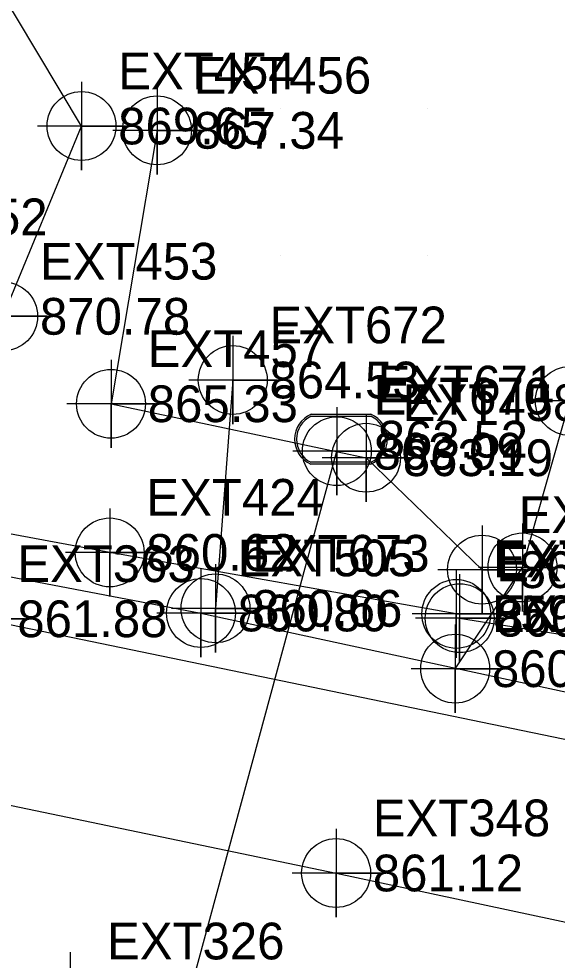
# Model space of a CAD drawing. Extents: x 1762120 to 1766775, y 709485 to 712965.
# Drawn here: x 1762642.2 to 1762678.8, y 712662 to 712726.1 of the extents above; entities that cross this region are included whole.
import ezdxf

# ---------------------------------------------------------------- set-up
doc = ezdxf.new("R2010")
doc.units = 0
for name, color, linetype in [('Exist DTM Breakline', 7, 'Continuous'), ('Exist DTM Breakline Cogo Elevation', 7, 'Continuous'), ('Exist DTM Breakline Cogo Number', 7, 'Continuous'), ('Exist DTM Breakline Cogo Point CELL', 7, 'Continuous'), ('Exist DTM Crownline', 7, 'Continuous'), ('Exist DTM Crownline Cogo Elevation', 7, 'Continuous'), ('Exist DTM Crownline Cogo Number', 7, 'Continuous'), ('Exist DTM Crownline Cogo Point CELL', 7, 'Continuous'), ('Exist DTM Drainline', 7, 'Continuous'), ('Exist DTM Drainline Cogo Elevation', 7, 'Continuous'), ('Exist DTM Drainline Cogo Number', 7, 'Continuous'), ('Exist DTM Drainline Cogo Point CELL', 7, 'Continuous'), ('Exist DTM QL2 LIDAR Elevation Point', 7, 'Continuous'), ('Exist Roads EOP', 7, 'Continuous'), ('Exist Roads EOP Cogo Elevation', 7, 'Continuous'), ('Exist Roads EOP Cogo Number', 7, 'Continuous'), ('Exist Roads EOP Cogo Point CELL', 7, 'Continuous'), ('Exist Roads EOP Other', 7, 'Continuous'), ('Exist Roads EOP Other Cogo Elevation', 7, 'Continuous'), ('Exist Roads EOP Other Cogo Number', 7, 'Continuous'), ('Exist Roads EOP Other Cogo Point CELL', 7, 'Continuous'), ('Exist Structure Minor Pipes RCP 12 Inch', 7, 'Continuous'), ('Exist Structure Minor Pipes RCP 12 Inch Cogo Comment', 7, 'Continuous'), ('Exist Structure Minor Pipes RCP 12 Inch Cogo Number', 7, 'Continuous'), ('Exist Structure Minor Pipes RCP 12 Inch Cogo Point CELL', 7, 'Continuous'), ('Exist Utilities Gas UG Line SUE LOS C', 7, 'Continuous'), ('Exist Utilities Gas UG Line SUE LOS C Cogo Elevation', 7, 'Continuous'), ('Exist Utilities Gas UG Line SUE LOS C Cogo Number', 7, 'Continuous'), ('Exist Utilities Gas UG Line SUE LOS C Cogo Point CELL', 7, 'Continuous'), ('Exist Utilities Water Meter CELL', 7, 'Continuous'), ('Exist Utilities Water Meter Cogo Elevation', 7, 'Continuous'), ('Exist Utilities Water Meter Cogo Number', 7, 'Continuous'), ('Exist Utilities Water UG Line SUE LOS C', 7, 'Continuous'), ('Exist Utilities Water UG Line SUE LOS C Cogo Elevation', 7, 'Continuous'), ('Exist Utilities Water UG Line SUE LOS C Cogo Number', 7, 'Continuous'), ('Exist Utilities Water UG Line SUE LOS C Cogo Point CELL', 7, 'Continuous')]:
    doc.layers.add(name, color=color, linetype=linetype)

msp = doc.modelspace()

# ---------------------------------------------------------------- linework, layer by layer
at = {"layer": 'Exist DTM Breakline'}
for points in [[(1762269.749, 712786.474), (1762271.078, 712779.952), (1762292.948, 712778.898), (1762320.699, 712776.029), (1762354.473, 712776.478), (1762388.07, 712765.375), (1762412.806, 712762.42), (1762443.018, 712756.652), (1762473.164, 712749.141), (1762494.52, 712743.823), (1762529.008, 712735.946), (1762558.208, 712731.146), (1762590.651, 712721.473), (1762629.546, 712708.877), (1762641.105, 712705.857), (1762646.432, 712718.811), (1762637.496, 712733.743)], [(1762651.575, 712718.518), (1762648.445, 712699.904), (1762665.806, 712696.23), (1762673.7, 712688.607)]]:
    msp.add_lwpolyline(points, dxfattribs=at)
at = {"layer": 'Exist DTM Breakline Cogo Point CELL'}
for points in [[(1762646.432, 712721.811), (1762646.432, 712715.811), (1762646.432, 712718.811), (1762649.432, 712718.811), (1762643.432, 712718.811)], [(1762651.575, 712721.518), (1762651.575, 712715.518), (1762651.575, 712718.518), (1762654.575, 712718.518), (1762648.575, 712718.518)], [(1762641.105, 712708.857), (1762641.105, 712702.857), (1762641.105, 712705.857), (1762644.105, 712705.857), (1762638.105, 712705.857)], [(1762648.445, 712702.904), (1762648.445, 712696.904), (1762648.445, 712699.904), (1762651.445, 712699.904), (1762645.445, 712699.904)], [(1762665.806, 712699.23), (1762665.806, 712693.23), (1762665.806, 712696.23), (1762668.806, 712696.23), (1762662.806, 712696.23)], [(1762673.7, 712691.607), (1762673.7, 712685.607), (1762673.7, 712688.607), (1762676.7, 712688.607), (1762670.7, 712688.607)]]:
    msp.add_lwpolyline(points, dxfattribs=at)
for centre in [(1762646.432, 712718.811), (1762651.575, 712718.518), (1762641.105, 712705.857), (1762648.445, 712699.904), (1762665.806, 712696.23), (1762673.7, 712688.607)]:
    msp.add_circle(centre, 2.344, dxfattribs=at)
at = {"layer": 'Exist DTM Crownline'}
msp.add_lwpolyline([(1762166.547, 712774.687), (1762217.293, 712763.929), (1762266.928, 712753.164), (1762315.989, 712742.645), (1762361.304, 712733.127), (1762409.518, 712722.711), (1762461.505, 712711.505), (1762512.117, 712700.307), (1762561.004, 712689.861), (1762611.478, 712678.845), (1762663.765, 712667.96), (1762715.266, 712656.972), (1762767.733, 712645.753), (1762820.16, 712634.416), (1762873.558, 712623.116), (1762907.318, 712615.867), (1762954.844, 712607.608), (1762970.656, 712604.722)], dxfattribs=at)
at = {"layer": 'Exist DTM Crownline Cogo Point CELL'}
msp.add_lwpolyline([(1762663.765, 712670.96), (1762663.765, 712664.96), (1762663.765, 712667.96), (1762666.765, 712667.96), (1762660.765, 712667.96)], dxfattribs=at)
msp.add_circle((1762663.765, 712667.96), 2.344, dxfattribs=at)
at = {"layer": 'Exist DTM Drainline'}
msp.add_lwpolyline([(1762671.946, 712685.598), (1762648.351, 712689.784), (1762626.117, 712693.918), (1762597.991, 712699.605), (1762564.625, 712706.389), (1762531.738, 712713.297), (1762498.472, 712720.195), (1762464.805, 712728.399), (1762431.886, 712735.459), (1762397.077, 712742.592), (1762358.768, 712750.543), (1762329.325, 712757.658), (1762298.805, 712765.159), (1762269.773, 712772.557), (1762248.853, 712776.111)], dxfattribs=at)
at = {"layer": 'Exist DTM Drainline Cogo Point CELL'}
for points in [[(1762648.351, 712692.784), (1762648.351, 712686.784), (1762648.351, 712689.784), (1762651.351, 712689.784), (1762645.351, 712689.784)], [(1762671.946, 712688.598), (1762671.946, 712682.598), (1762671.946, 712685.598), (1762674.946, 712685.598), (1762668.946, 712685.598)]]:
    msp.add_lwpolyline(points, dxfattribs=at)
for centre in [(1762648.351, 712689.784), (1762671.946, 712685.598)]:
    msp.add_circle(centre, 2.344, dxfattribs=at)
at = {"layer": 'Exist DTM QL2 LIDAR Elevation Point'}
for p, q in [((1762660, 712720), (1762660, 712720)), ((1762670, 712720), (1762670, 712720)), ((1762660, 712710), (1762660, 712710)), ((1762670, 712710), (1762670, 712710)), ((1762660, 712700), (1762660, 712700)), ((1762670, 712700), (1762670, 712700))]:
    msp.add_line(p, q, dxfattribs=at)
at = {"layer": 'Exist Roads EOP'}
msp.add_lwpolyline([(1762972.643, 712616.327), (1762930.479, 712622.907), (1762881.99, 712633.196), (1762831.971, 712644.063), (1762782.816, 712654.409), (1762735.737, 712664.412), (1762686.68, 712675.525), (1762639.564, 712685.265), (1762589.399, 712696.151), (1762546.232, 712705.49), (1762496.404, 712716.081), (1762446.151, 712726.895), (1762396.234, 712737.694), (1762346.428, 712748.231), (1762295.972, 712759.182), (1762245.105, 712770.099), (1762193.683, 712780.972), (1762169.004, 712786.417)], dxfattribs=at)
at = {"layer": 'Exist Roads EOP Cogo Point CELL'}
for points in [[(1762639.564, 712688.265), (1762639.564, 712682.265), (1762639.564, 712685.265), (1762642.564, 712685.265), (1762636.564, 712685.265)], [(1762645.671, 712662.578), (1762645.671, 712656.578), (1762645.671, 712659.578), (1762648.671, 712659.578), (1762642.671, 712659.578)]]:
    msp.add_lwpolyline(points, dxfattribs=at)
at = {"layer": 'Exist Roads EOP Other'}
msp.add_lwpolyline([(1762671.874, 712681.868), (1762676.456, 712688.763), (1762679.673, 712700.094), (1762681.831, 712712.591)], dxfattribs=at)
at = {"layer": 'Exist Roads EOP Other Cogo Point CELL'}
for points in [[(1762679.673, 712703.094), (1762679.673, 712697.094), (1762679.673, 712700.094), (1762682.673, 712700.094), (1762676.673, 712700.094)], [(1762676.456, 712691.763), (1762676.456, 712685.763), (1762676.456, 712688.763), (1762679.456, 712688.763), (1762673.456, 712688.763)], [(1762671.874, 712684.868), (1762671.874, 712678.868), (1762671.874, 712681.868), (1762674.874, 712681.868), (1762668.874, 712681.868)]]:
    msp.add_lwpolyline(points, dxfattribs=at)
for centre in [(1762679.673, 712700.094), (1762676.456, 712688.763), (1762671.874, 712681.868)]:
    msp.add_circle(centre, 2.344, dxfattribs=at)
at = {"layer": 'Exist Structure Minor Pipes RCP 12 Inch'}
msp.add_line((1762672.176, 712685.305), (1762690.378, 712682.399), dxfattribs=at)
at = {"layer": 'Exist Structure Minor Pipes RCP 12 Inch Cogo Point CELL'}
msp.add_lwpolyline([(1762672.176, 712688.305), (1762672.176, 712682.305), (1762672.176, 712685.305), (1762675.176, 712685.305), (1762669.176, 712685.305)], dxfattribs=at)
msp.add_circle((1762672.176, 712685.305), 2.344, dxfattribs=at)
at = {"layer": 'Exist Utilities Gas UG Line SUE LOS C'}
msp.add_line((1762656.73, 712701.52), (1762655.552, 712685.976), dxfattribs=at)
msp.add_lwpolyline([(1762186.211, 712786.583), (1762241.953, 712774.527), (1762368.977, 712745.664), (1762446.664, 712730.32), (1762499.183, 712718.668), (1762560.329, 712705.064), (1762614.265, 712693.34), (1762654.566, 712685.659), (1762695.772, 712676.761), (1762747.569, 712665.846), (1762826.119, 712649.314), (1762887.977, 712636.743)], dxfattribs=at)
at = {"layer": 'Exist Utilities Gas UG Line SUE LOS C Cogo Point CELL'}
for points in [[(1762656.73, 712704.52), (1762656.73, 712698.52), (1762656.73, 712701.52), (1762659.73, 712701.52), (1762653.73, 712701.52)], [(1762655.552, 712688.976), (1762655.552, 712682.976), (1762655.552, 712685.976), (1762658.552, 712685.976), (1762652.552, 712685.976)], [(1762654.566, 712688.659), (1762654.566, 712682.659), (1762654.566, 712685.659), (1762657.566, 712685.659), (1762651.566, 712685.659)]]:
    msp.add_lwpolyline(points, dxfattribs=at)
for centre in [(1762656.73, 712701.52), (1762655.552, 712685.976), (1762654.566, 712685.659)]:
    msp.add_circle(centre, 2.344, dxfattribs=at)
at = {"layer": 'Exist Utilities Water Meter CELL'}
msp.add_line((1762664.102, 712697.491), (1762664.102, 712697.491), dxfattribs=at)
for points in [[(1762662.065, 712699.191), (1762666.14, 712699.191)], [(1762662.065, 712699.053), (1762666.14, 712699.053)], [(1762666.14, 712695.928), (1762662.039, 712695.928)], [(1762666.14, 712695.791), (1762662.039, 712695.791)]]:
    msp.add_lwpolyline(points, dxfattribs=at)
for centre, radius, start, end in [((1762662.795, 712697.486), 1.855, 113.17804, 245.97939), ((1762662.806, 712697.485), 1.735, 115.30093, 243.78236), ((1762665.395, 712697.492), 1.856, 293.64832, 66.30838), ((1762665.407, 712697.491), 1.726, 295.12717, 64.87283)]:
    msp.add_arc(centre, radius, start, end, dxfattribs=at)
at = {"layer": 'Exist Utilities Water UG Line SUE LOS C'}
msp.add_line((1762652.797, 712656.06), (1762663.818, 712696.673), dxfattribs=at)
at = {"layer": 'Exist Utilities Water UG Line SUE LOS C Cogo Point CELL'}
msp.add_lwpolyline([(1762663.818, 712699.673), (1762663.818, 712693.673), (1762663.818, 712696.673), (1762666.818, 712696.673), (1762660.818, 712696.673)], dxfattribs=at)
msp.add_circle((1762663.818, 712696.673), 2.344, dxfattribs=at)

# ---------------------------------------------------------------- texts
at = {"layer": 'Exist DTM Breakline Cogo Elevation'}
for s, p in [('869.65', (1762648.932, 712717.561)), ('867.34', (1762654.075, 712717.268)), ('870.78', (1762643.605, 712704.607)), ('865.33', (1762650.945, 712698.654)), ('863.19', (1762668.306, 712694.98)), ('861.20', (1762676.2, 712687.357))]:
    msp.add_text(s, height=2.5, dxfattribs=at).set_placement(p)
at = {"layer": 'Exist DTM Breakline Cogo Number'}
for s, p in [('EXT454', (1762648.932, 712721.311)), ('EXT456', (1762654.075, 712721.018)), ('EXT452', (1762632.046, 712711.377)), ('EXT453', (1762643.605, 712708.357)), ('EXT457', (1762650.945, 712702.404)), ('EXT458', (1762668.306, 712698.73)), ('EXT459', (1762676.2, 712691.107))]:
    msp.add_text(s, height=2.5, dxfattribs=at).set_placement(p)
at = {"layer": 'Exist DTM Crownline Cogo Elevation'}
msp.add_text('861.12', height=2.5, dxfattribs=at).set_placement((1762666.265, 712666.71))
at = {"layer": 'Exist DTM Crownline Cogo Number'}
msp.add_text('EXT348', height=2.5, dxfattribs=at).set_placement((1762666.265, 712670.46))
at = {"layer": 'Exist DTM Drainline Cogo Elevation'}
for s, p in [('860.62', (1762650.851, 712688.534)), ('859.65', (1762674.446, 712684.348))]:
    msp.add_text(s, height=2.5, dxfattribs=at).set_placement(p)
at = {"layer": 'Exist DTM Drainline Cogo Number'}
for s, p in [('EXT424', (1762650.851, 712692.284)), ('EXT423', (1762674.446, 712688.098))]:
    msp.add_text(s, height=2.5, dxfattribs=at).set_placement(p)
at = {"layer": 'Exist Roads EOP Cogo Elevation'}
msp.add_text('861.88', height=2.5, dxfattribs=at).set_placement((1762642.064, 712684.015))
at = {"layer": 'Exist Roads EOP Cogo Number'}
for s, p in [('EXT363', (1762642.064, 712687.765)), ('EXT326', (1762648.171, 712662.078))]:
    msp.add_text(s, height=2.5, dxfattribs=at).set_placement(p)
at = {"layer": 'Exist Roads EOP Other Cogo Elevation'}
msp.add_text('860.53', height=2.5, dxfattribs=at).set_placement((1762674.374, 712680.618))
at = {"layer": 'Exist Roads EOP Other Cogo Number'}
msp.add_text('EXT413', height=2.5, dxfattribs=at).set_placement((1762674.374, 712684.368))
at = {"layer": 'Exist Structure Minor Pipes RCP 12 Inch Cogo Comment'}
msp.add_text('860.37', height=2.5, dxfattribs=at).set_placement((1762674.676, 712684.055))
at = {"layer": 'Exist Structure Minor Pipes RCP 12 Inch Cogo Number'}
msp.add_text('EXT417', height=2.5, dxfattribs=at).set_placement((1762674.676, 712687.805))
at = {"layer": 'Exist Utilities Gas UG Line SUE LOS C Cogo Elevation'}
for s, p in [('864.53', (1762659.23, 712700.27)), ('860.66', (1762658.052, 712684.726)), ('860.80', (1762657.066, 712684.409))]:
    msp.add_text(s, height=2.5, dxfattribs=at).set_placement(p)
at = {"layer": 'Exist Utilities Gas UG Line SUE LOS C Cogo Number'}
for s, p in [('EXT672', (1762659.23, 712704.02)), ('EXT673', (1762658.052, 712688.476)), ('EXT505', (1762657.066, 712688.159))]:
    msp.add_text(s, height=2.5, dxfattribs=at).set_placement(p)
at = {"layer": 'Exist Utilities Water Meter Cogo Elevation'}
msp.add_text('863.52', height=2.5, dxfattribs=at).set_placement((1762666.602, 712696.241))
at = {"layer": 'Exist Utilities Water Meter Cogo Number'}
msp.add_text('EXT671', height=2.5, dxfattribs=at).set_placement((1762666.602, 712699.991))
at = {"layer": 'Exist Utilities Water UG Line SUE LOS C Cogo Elevation'}
msp.add_text('863.09', height=2.5, dxfattribs=at).set_placement((1762666.318, 712695.423))
at = {"layer": 'Exist Utilities Water UG Line SUE LOS C Cogo Number'}
msp.add_text('EXT670', height=2.5, dxfattribs=at).set_placement((1762666.318, 712699.173))

doc.saveas('drawing.dxf')
